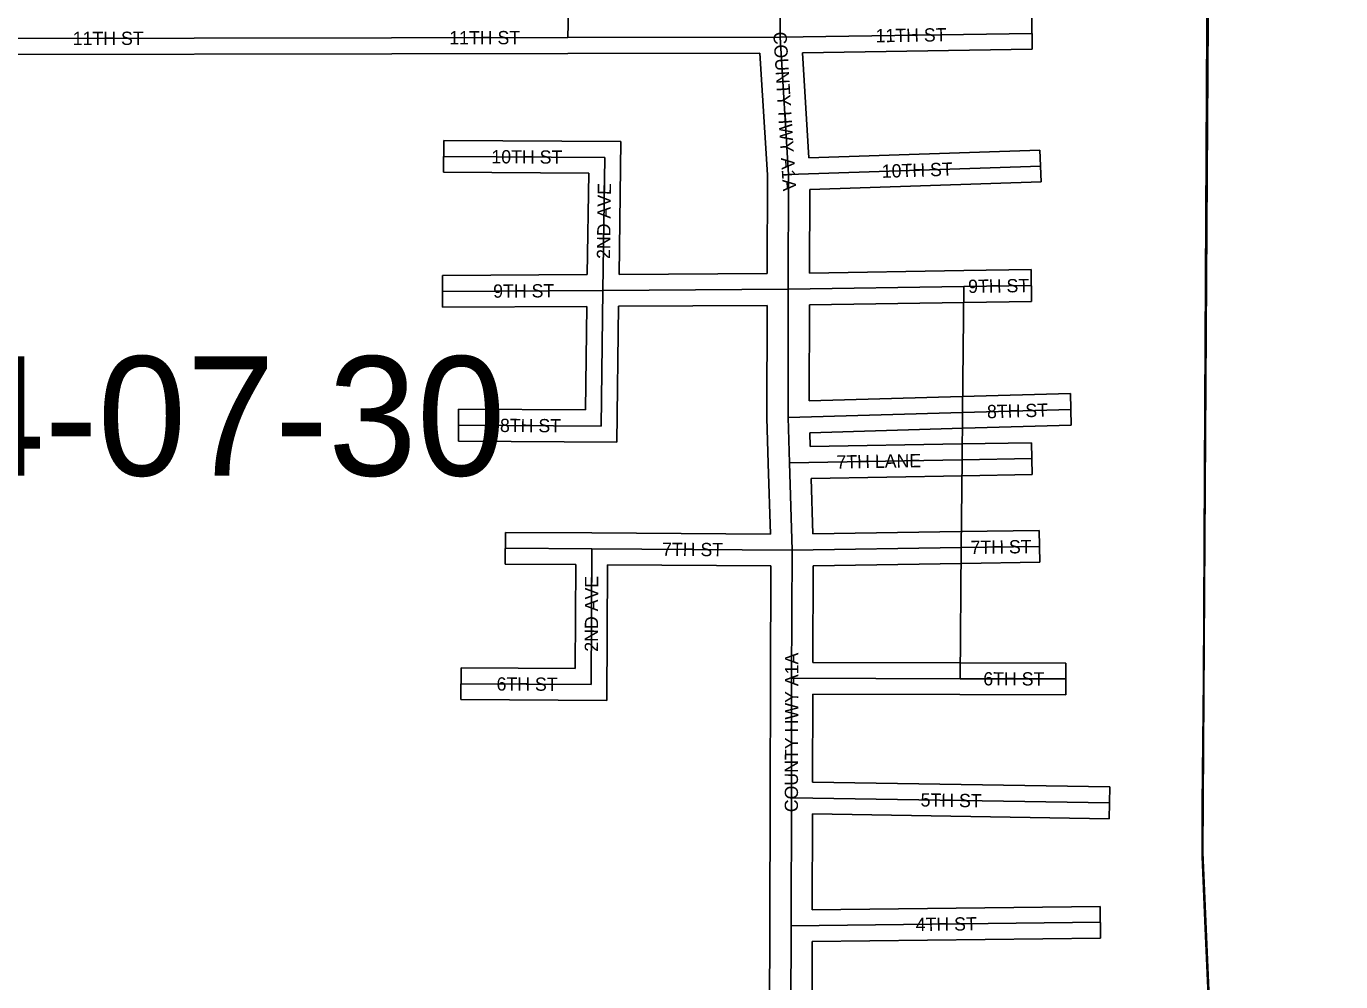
# Model space of a CAD drawing. Extents: x 418523 to 616617, y 1878279 to 2196743.
# Drawn here: x 570042 to 572522, y 2004425 to 2006226 of the extents above; entities that cross this region are included whole.
import ezdxf

# ---------------------------------------------------------------- set-up
doc = ezdxf.new("R2010")
doc.units = 0
for name, color, linetype in [('Level 2', 7, 'Continuous'), ('Level 22', 7, 'Continuous'), ('Level 23', 7, 'Continuous'), ('Level 31', 7, 'Continuous'), ('Level 32', 7, 'Continuous'), ('Level 34', 7, 'Continuous'), ('Level 5', 7, 'Continuous'), ('Level 55', 7, 'Continuous'), ('Level 8', 7, 'Continuous')]:
    doc.layers.add(name, color=color, linetype=linetype)

msp = doc.modelspace()

# ---------------------------------------------------------------- linework, layer by layer
at = {"layer": 'Level 22'}
for p, q in [((571464.294, 2006205.379), (571464.61, 2006342.477)), ((571480.184, 2005946.781), (571464.294, 2006205.379)), ((571479.684, 2005730.042), (571480.184, 2005946.781)), ((571479.128, 2005488.576), (571479.684, 2005730.042)), ((571481.784, 2005402.746), (571479.128, 2005488.576)), ((571486.794, 2005238.361), (571481.784, 2005402.746)), ((571485.919, 2004996.531), (571486.794, 2005238.361)), ((571485.401, 2004771.427), (571485.919, 2004996.531)), ((571484.844, 2004529.597), (571485.401, 2004771.427)), ((571484.288, 2004288.129), (571484.844, 2004529.597))]:
    msp.add_line(p, q, dxfattribs=at)
at = {"layer": 'Level 23'}
for p, q in [((571440.181, 2005945.599), (571426.066, 2006175.326)), ((571518.339, 2005978.052), (571506.176, 2006176.015)), ((571439.753, 2005759.803), (571440.181, 2005945.599)), ((571519.756, 2005760.702), (571520.119, 2005918.077)), ((571439.127, 2005488.002), (571439.614, 2005699.8)), ((571519.201, 2005519.734), (571519.619, 2005700.69)), ((571441.802, 2005401.509), (571439.126, 2005488.002)), ((571520.854, 2005433.445), (571520.042, 2005459.731)), ((571445.854, 2005268.613), (571441.802, 2005401.527)), ((571525.882, 2005268.941), (571522.696, 2005373.466)), ((571445.919, 2004996.676), (571446.686, 2005208.606)), ((571526.029, 2005026.438), (571526.689, 2005208.946)), ((571445.4, 2004771.52), (571445.919, 2004996.623)), ((571525.47, 2004800.781), (571525.852, 2004966.437)), ((571444.844, 2004529.689), (571445.4, 2004771.52)), ((571524.915, 2004560.081), (571525.331, 2004740.774)), ((571444.29, 2004288.956), (571444.844, 2004529.689)), ((571524.358, 2004318.007), (571524.777, 2004500.073))]:
    msp.add_line(p, q, dxfattribs=at)
at = {"layer": 'Level 31'}
for p, q in [((571063.893, 2006204.851), (571070.205, 2006466.671)), ((571464.294, 2006205.379), (571939.529, 2006212.648)), ((570731.333, 2006204.171), (569643.304, 2006202.359)), ((571063.893, 2006204.851), (570731.333, 2006204.171)), ((571464.294, 2006205.379), (571063.893, 2006204.851)), ((570829.409, 2005980.656), (571133.432, 2005978.859)), ((571133.432, 2005978.859), (571129.998, 2005727.943)), ((571480.184, 2005946.781), (571955.441, 2005962.416)), ((571810.99, 2005735.461), (571938.123, 2005737.351)), ((571129.998, 2005727.943), (570827.232, 2005726.101)), ((571129.998, 2005727.943), (571126.553, 2005472.3)), ((571479.684, 2005730.042), (571129.998, 2005727.943)), ((571479.684, 2005730.042), (571810.99, 2005735.461)), ((571479.128, 2005488.576), (571808.543, 2005497.998)), ((571808.543, 2005497.998), (572012.724, 2005503.711)), ((571126.553, 2005472.3), (570857.399, 2005474.016)), ((571481.784, 2005402.746), (571807.704, 2005408.54)), ((571807.704, 2005408.54), (571938.959, 2005410.784)), ((571108.898, 2005240.69), (570945.945, 2005241.796)), ((571486.794, 2005238.361), (571806.056, 2005243.08)), ((571806.056, 2005243.08), (571953.481, 2005245.286)), ((571108.898, 2005240.69), (571107.671, 2004985.041)), ((571486.794, 2005238.361), (571108.898, 2005240.69)), ((571803.586, 2004995.798), (571485.919, 2004996.531)), ((572002.999, 2004995.34), (571803.586, 2004995.798)), ((571107.671, 2004985.041), (570862.289, 2004986.34)), ((572085.528, 2004761.682), (571485.401, 2004771.427)), ((572068.527, 2004536.618), (571484.844, 2004529.597))]:
    msp.add_line(p, q, dxfattribs=at)
at = {"layer": 'Level 32'}
for p, q in [((571939.07, 2006242.645), (571939.989, 2006182.651)), ((570731.384, 2006174.17), (569673.738, 2006172.408)), ((571063.954, 2006174.851), (570731.395, 2006174.17)), ((571426.065, 2006175.327), (571063.932, 2006174.851)), ((571506.176, 2006176.015), (571939.989, 2006182.651)), ((570829.586, 2006010.656), (570829.232, 2005950.656)), ((570829.586, 2006010.656), (571163.844, 2006008.68)), ((571163.844, 2006008.679), (571160.415, 2005758.126)), ((571518.339, 2005978.052), (571954.455, 2005992.399)), ((571954.455, 2005992.399), (571956.429, 2005932.431)), ((570829.232, 2005950.656), (571103.02, 2005949.036)), ((571103.02, 2005949.036), (571100.403, 2005757.763)), ((571520.119, 2005918.077), (571956.429, 2005932.431)), ((571519.756, 2005760.702), (571810.499, 2005765.457)), ((571810.544, 2005765.458), (571937.677, 2005767.348)), ((571937.677, 2005767.348), (571938.569, 2005707.352)), ((571100.403, 2005757.763), (570827.05, 2005756.101)), ((570827.415, 2005696.101), (570827.05, 2005756.101)), ((571439.753, 2005759.803), (571160.415, 2005758.126)), ((571099.589, 2005697.756), (570827.415, 2005696.101)), ((571099.589, 2005697.756), (571096.958, 2005502.488)), ((571159.599, 2005698.118), (571156.15, 2005442.109)), ((571439.614, 2005699.8), (571159.599, 2005698.118)), ((571519.619, 2005700.69), (571811.482, 2005705.463)), ((571811.437, 2005705.462), (571938.569, 2005707.352)), ((571519.201, 2005519.734), (571807.685, 2005527.986)), ((571807.704, 2005527.986), (572011.884, 2005533.699)), ((572011.884, 2005533.699), (572013.563, 2005473.721)), ((570857.208, 2005444.015), (570857.589, 2005504.016)), ((571096.957, 2005502.489), (570857.589, 2005504.016)), ((571520.041, 2005459.731), (571809.401, 2005468.009)), ((571809.383, 2005468.009), (572013.563, 2005473.721)), ((571156.151, 2005442.108), (570857.208, 2005444.015)), ((571807.191, 2005438.536), (571938.447, 2005440.78)), ((571938.447, 2005440.78), (571939.472, 2005380.788)), ((571520.854, 2005433.446), (571807.17, 2005438.536)), ((571522.697, 2005373.466), (571808.238, 2005378.543)), ((571808.217, 2005378.543), (571939.472, 2005380.788)), ((570945.743, 2005211.796), (570946.149, 2005271.796)), ((571109.101, 2005270.69), (570946.149, 2005271.796)), ((571445.854, 2005268.613), (571109.083, 2005270.69)), ((571525.883, 2005268.941), (571805.613, 2005273.077)), ((571805.607, 2005273.076), (571953.032, 2005275.283)), ((571953.032, 2005275.283), (571953.93, 2005215.289)), ((571078.755, 2005210.892), (570945.743, 2005211.796)), ((571078.755, 2005210.892), (571077.816, 2005015.201)), ((571138.754, 2005210.504), (571137.529, 2004954.882)), ((571446.686, 2005208.606), (571138.754, 2005210.504)), ((571526.689, 2005208.946), (571806.499, 2005213.081)), ((571806.505, 2005213.082), (571953.93, 2005215.289)), ((571803.655, 2005025.798), (571526.029, 2005026.438)), ((572003.069, 2005025.34), (571803.655, 2005025.798)), ((572002.93, 2004965.339), (572003.069, 2005025.34)), ((570862.132, 2004956.339), (570862.449, 2005016.34)), ((571077.815, 2005015.2), (570862.449, 2005016.34)), ((571137.529, 2004954.882), (570862.132, 2004956.339)), ((571803.517, 2004965.797), (571525.852, 2004966.437)), ((572002.93, 2004965.339), (571803.517, 2004965.797)), ((572086.014, 2004791.679), (571525.47, 2004800.781)), ((572085.041, 2004731.685), (572086.014, 2004791.679)), ((572085.041, 2004731.685), (571525.332, 2004740.773)), ((572068.166, 2004566.616), (571524.915, 2004560.081)), ((572068.889, 2004506.619), (572068.166, 2004566.616)), ((572068.889, 2004506.619), (571524.777, 2004500.073))]:
    msp.add_line(p, q, dxfattribs=at)
at = {"layer": 'Level 5'}
msp.add_lwpolyline([(572278.004, 2007218.757), (572261.409, 2004667.87), (572323.526, 2003250.488), (572348.437, 2003217.048), (572370.614, 2002341.668), (572394.998, 2002149.835), (572461.476, 1999498.646), (572465.57, 1998189.806), (572518.829, 1996605.731)], dxfattribs=at)
at = {"layer": 'Level 55'}
for p, q in [((571810.99, 2005735.461), (571808.543, 2005497.998)), ((571808.543, 2005497.998), (571807.704, 2005408.54)), ((571807.704, 2005408.54), (571806.056, 2005243.08)), ((571806.056, 2005243.08), (571803.586, 2004995.798))]:
    msp.add_line(p, q, dxfattribs=at)
at = {"layer": 'Level 8'}
msp.add_lwpolyline([(572270.578, 2006461.581), (572265.594, 2005510.559), (572262.604, 2004994.547), (572260.608, 2004759.541), (572260.609, 2004660.54), (572265.612, 2004539.536), (572276.616, 2004285.531), (572292.623, 2003941.524), (572309.63, 2003564.516), (572323.636, 2003243.508), (572348.638, 2003210.508), (572370.654, 2002335.488), (572395.658, 2002143.484), (572435.687, 2000573.449), (572445.694, 2000181.441), (572462.707, 1999491.425), (572463.708, 1999433.424), (572467.73, 1998183.396), (572521.759, 1996599.361)], dxfattribs=at)

# ---------------------------------------------------------------- texts
at = {"layer": 'Level 2'}
msp.add_text('34-07-30', height=225, dxfattribs=at).set_placement((569741.803, 2005378.773))
at = {"layer": 'Level 34'}
for s, height, rotation, p in [('11TH ST', 25, 0.094697, (570129.701, 2006190.67)), ('11TH ST', 24.9992, 0.116622, (570840.003, 2006191.895)), ('COUNTY HWY A1A', 25, 273.515028, (571451.183, 2006214.972)), ('11TH ST', 24.9992, 0.875608, (571644.474, 2006195.636)), ('10TH ST', 25, 359.660542, (570919.456, 2005967.626)), ('10TH ST', 25, 1.883336, (571656.367, 2005940.071)), ('2ND AVE', 25, 89.214903, (571143.306, 2005787.095)), ('9TH ST', 25, 0.347872, (570922.944, 2005714.185)), ('9TH ST', 25, 0.850842, (571819, 2005723.08)), ('8TH ST', 25, 1.601997, (571854.784, 2005486.787)), ('8TH ST', 25, 359.633933, (570935.676, 2005461.017)), ('7TH LANE', 25, 1.017822, (571570.644, 2005391.826)), ('7TH ST', 25, 359.646108, (571241.39, 2005227.375)), ('7TH ST', 25, 0.856833, (571823.583, 2005230.842)), ('2ND AVE', 25, 89.72425, (571120.465, 2005046.666)), ('COUNTY HWY A1A', 25, 89.86695, (571497.835, 2004744.03)), ('6TH ST', 24.9992, 359.696339, (570929.172, 2004973.486)), ('6TH ST', 24.9992, 359.867603, (571847.517, 2004983.2)), ('5TH ST', 25, 359.068958, (571729.048, 2004754.971)), ('4TH ST', 25, 0.688422, (571720.146, 2004519.928))]:
    msp.add_text(s, height=height, rotation=rotation, dxfattribs=at).set_placement(p)

doc.saveas('drawing.dxf')
